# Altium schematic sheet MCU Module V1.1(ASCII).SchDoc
size 420 x 297 mm
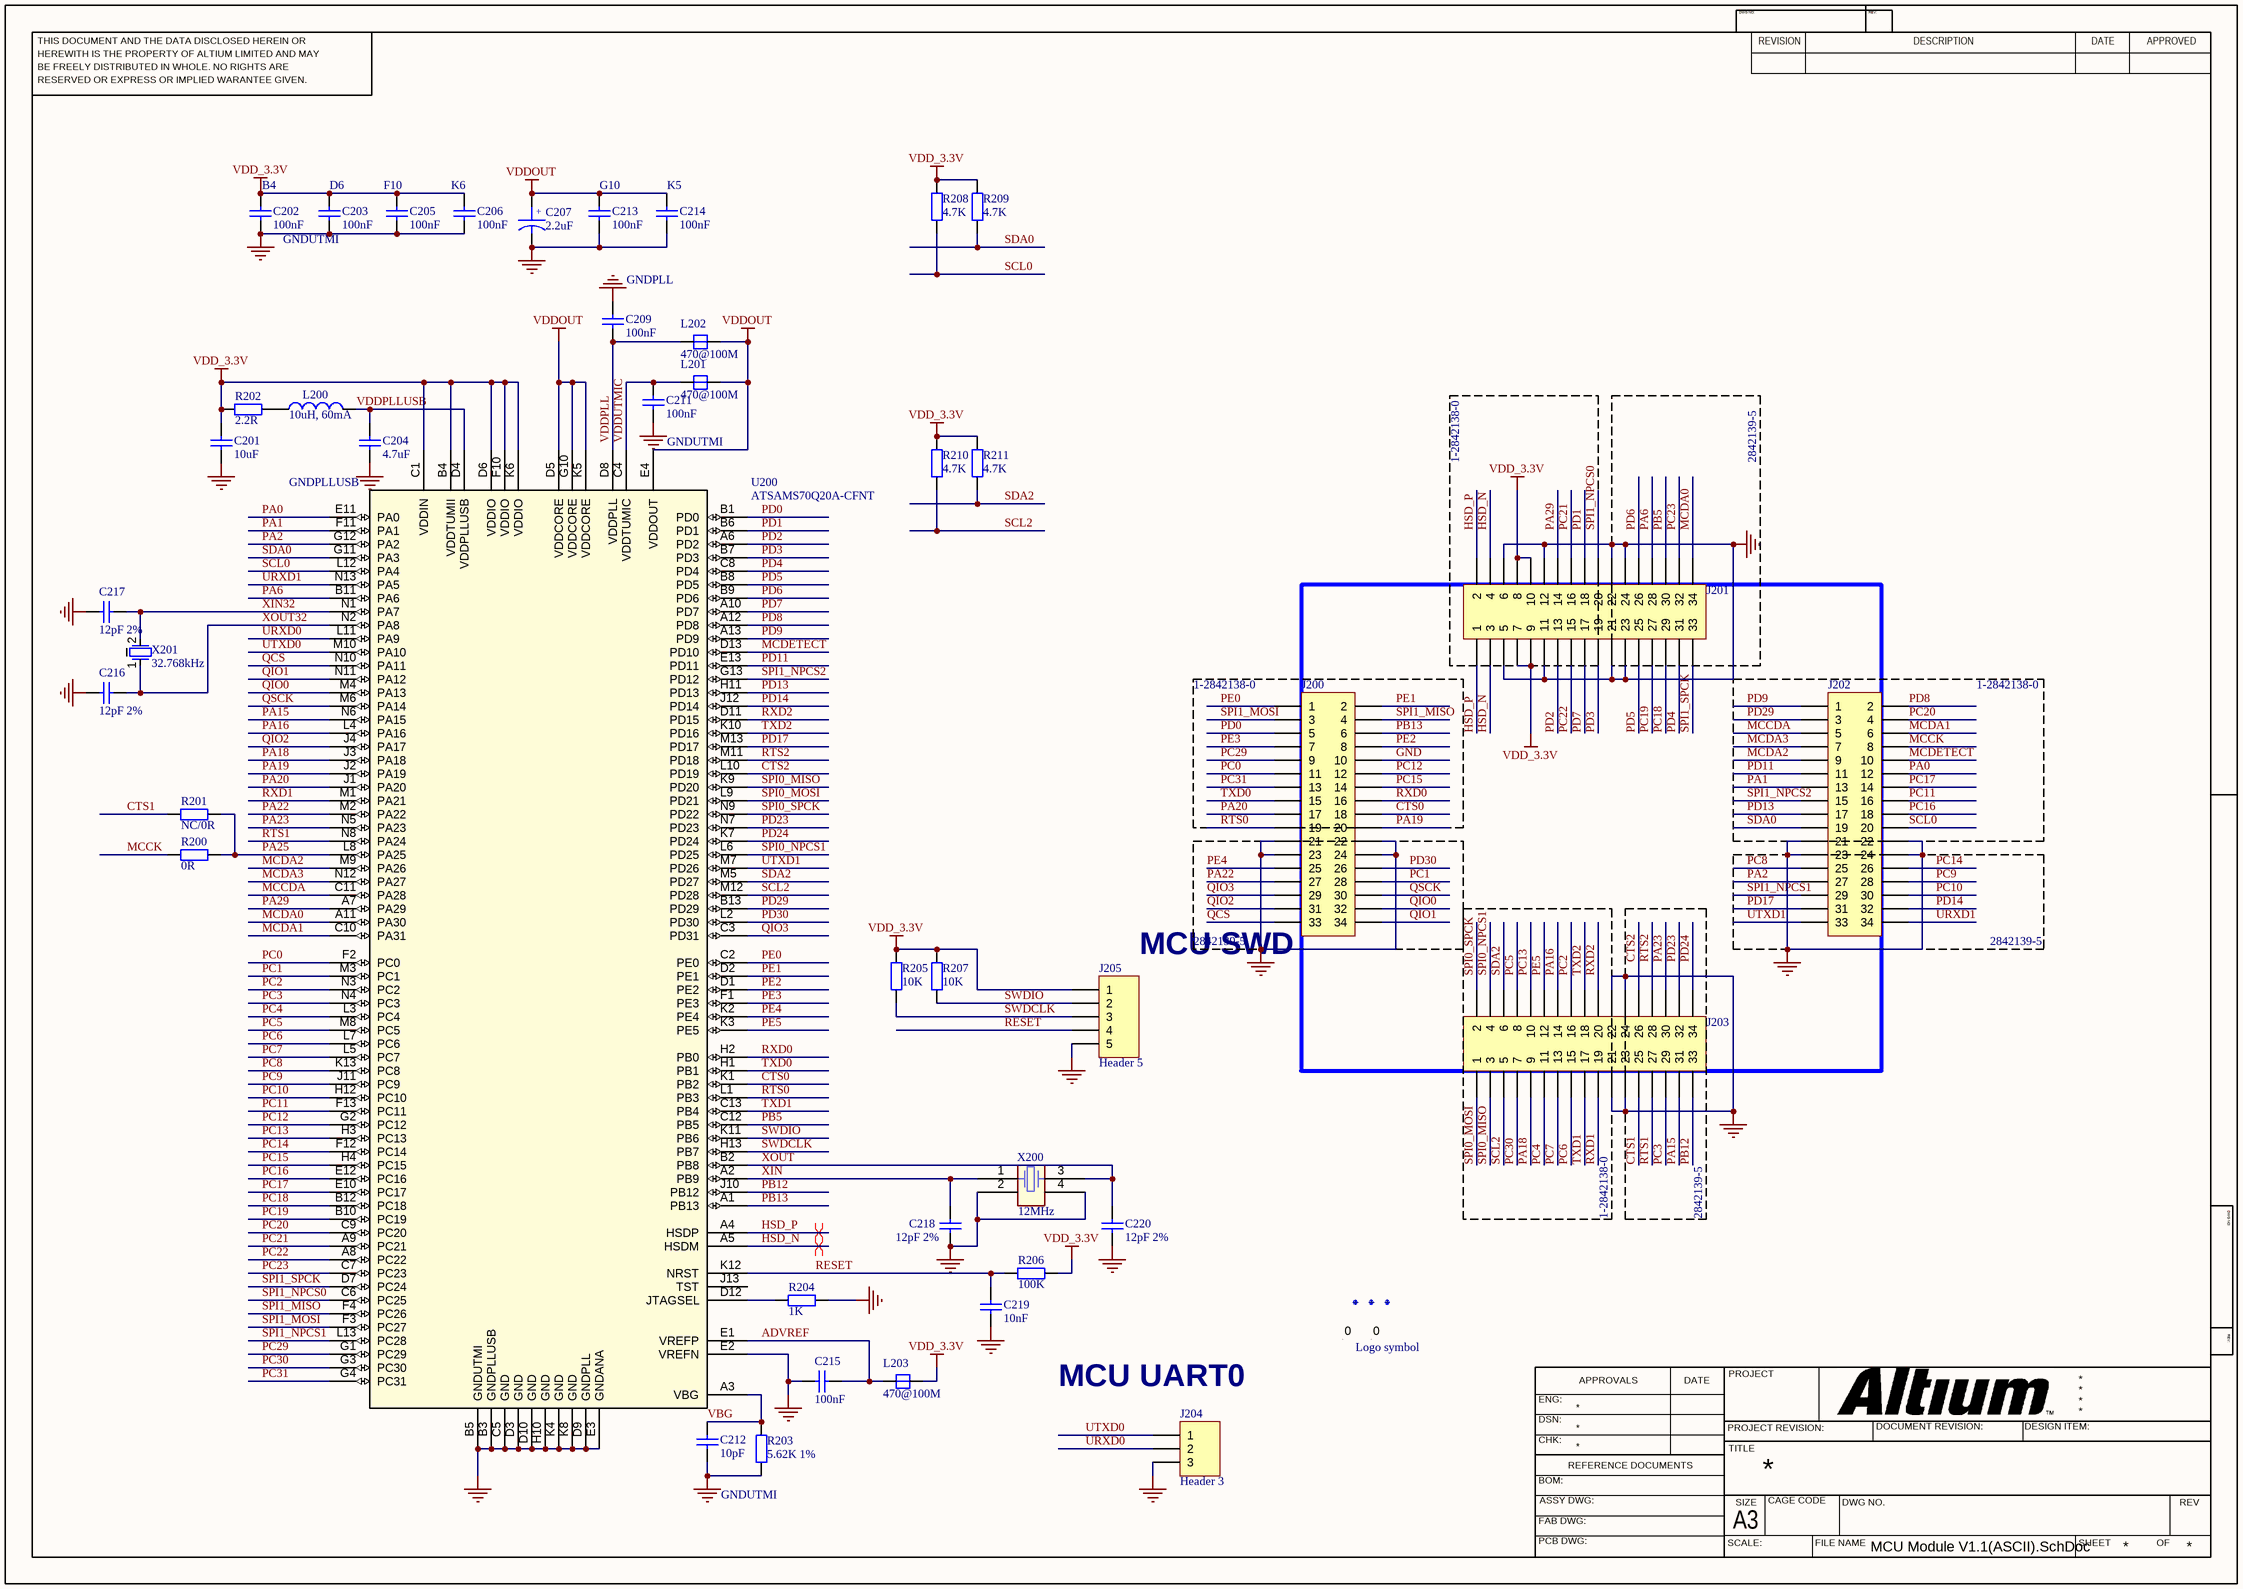
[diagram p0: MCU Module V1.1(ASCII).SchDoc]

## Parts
C201  10uF  [C_0805_2012Metric]
C202  100nF  [C_0805_2012Metric]
C203  100nF  [C_0805_2012Metric]
C204  4.7uF  [C_0805_2012Metric]
C205  100nF  [C_0805_2012Metric]
C206  100nF  [C_0805_2012Metric]
C207  2.2uF  [C_TAN_1206_3216METRIC]
C209  100nF  [C_0805_2012Metric]
C211  100nF  [C_0805_2012Metric]
C212  10pF  [C_0805_2012Metric]
C213  100nF  [C_0805_2012Metric]
C214  100nF  [C_0805_2012Metric]
C215  100nF  [C_0805_2012Metric]
C216  12pF 2%  [C_0805_2012Metric]
C217  12pF 2%  [C_0805_2012Metric]
C218  12pF 2%  [C_0805_2012Metric]
C219  10nF  [C_0805_2012Metric]
C220  12pF 2%  [C_0805_2012Metric]
Fid1  Fiducial mark  [Fiducial_1mm_Mask2mm]  (value not drawn)  (no BOM)
Fid2  Fiducial mark  [Fiducial_1mm_Mask2mm]  (value not drawn)  (no BOM)
Fid3  Fiducial mark  [Fiducial_1mm_Mask2mm]  (value not drawn)  (no BOM)
J200  Header 17X2  [HDR-TH_34P-P2.00-V-M-R2-C17-S2.00 - MALE]  (value not drawn)
J201  Header 17X2  [HDR-TH_34P-P2.00-V-M-R2-C17-S2.00 - MALE]  (value not drawn)
J202  Header 17X2  [HDR-TH_34P-P2.00-V-M-R2-C17-S2.00 - MALE]  (value not drawn)
J203  Header 17X2  [HDR-TH_34P-P2.00-V-M-R2-C17-S2.00 - MALE]  (value not drawn)
J204  Header 3  [PinHeader_1x03_P2.54mm_Vertical]
J205  Header 5  [PinHeader_1x05_P2.54mm_Vertical]
L200  10uH, 60mA  [L_0603_1608Metric]
L201  470@100M  [L_0603_1608Metric]
L202  470@100M  [L_0603_1608Metric]
L203  470@100M  [L_0603_1608Metric]
Logo_Bot?  Logo symbol  [CE-Logo_8.5x6mm_SilkScreen]  (value not drawn)
Logo_Top?  Logo symbol  [WEEE-Logo_4.2x6mm_SilkScreen]
R200  0R  [R_0805_2012Metric]
R201  NC/0R  [R_0805_2012Metric]
R202  2.2R  [R_0805_2012Metric]
R203  5.62K 1%  [R_0805_2012Metric]
R204  1K  [R_0805_2012Metric]
R205  10K  [R_0805_2012Metric]
R206  100K  [R_0805_2012Metric]
R207  10K  [R_0805_2012Metric]
R208  4.7K  [R_0805_2012Metric]
R209  4.7K  [R_0805_2012Metric]
R210  4.7K  [R_0805_2012Metric]
R211  4.7K  [R_0805_2012Metric]
U200  ATSAMS70Q20A-CFNT  [UFBGA144(6x6mm)]
X200  12MHz  [CRY-3225]
X201  32.768kHz  [Crystal 1.8x6mmm]

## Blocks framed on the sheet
1-2842138-0: J201
1-2842138-0: J200
1-2842138-0: J202

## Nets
GND: C201.2 C202.2 C203.2 C204.2 C205.2 C206.2 C207.2 C209.1 C211.2 C212.1 C213.2 C214.2 C215.1 C216.1 C217.1 C218.1 C219.2 C220.1 J200.10 J200.21 J200.22 J200.23 J200.24 J201.5 J201.6 J201.11 J201.12 J201.21 J201.22 J201.23 J201.24 J202.21 J202.22 J202.23 J202.24 J203.21 J203.22 J203.23 J203.24 J204.3 J205.5 R203.1 R204.1 U200.B3(GNDPLLUSB) U200.B5(GNDUTMI) U200.C5(GND) U200.D3(GND) U200.D9(GNDPLL) U200.D10(GND) U200.E2(VREFN) U200.E3(GNDANA) U200.H10(GND) U200.K4(GND) U200.K8(GND) X200.2 X200.4
VDD_3.3V: C201.1 C202.1 C203.1 C205.1 C206.1 J201.7 J201.8 J201.9 J201.10 J205.1 L203.2 R202.2 R205.2 R206.1 R207.2 R208.2 R209.2 R210.2 R211.2 U200.B4(VDDTUMII) U200.C1(VDDIN) U200.D6(VDDIO) U200.F10(VDDIO) U200.K6(VDDIO)
VDDOUT: C207.1 C213.1 C214.1 L201.2 L202.2 U200.D5(VDDCORE) U200.E4(VDDOUT) U200.G10(VDDCORE) U200.K5(VDDCORE)
ADVREF: C215.2 L203.1 U200.E1(VREFP)
CTS0: J200.18 U200.K1(PB2)
CTS1: J203.25 R201.2
CTS2: J203.26 U200.L10(PD19)
HSD_N: J201.3 J201.4 U200.A5(HSDM)
HSD_P: J201.1 J201.2 U200.A4(HSDP)
MCCDA: J202.5 U200.C11(PA28)
MCCK: J202.8 R200.2
MCDA0: J201.34 U200.A11(PA30)
MCDA1: J202.6 U200.C10(PA31)
MCDA2: J202.9 U200.M9(PA26)
MCDA3: J202.7 U200.N12(PA27)
MCDETECT: J202.10 U200.D13(PD10)
PA0: J202.12 U200.E11(PA0)
PA1: J202.13 U200.F11(PA1)
PA2: J202.27 U200.G12(PA2)
PA6: J201.28 U200.B11(PA6)
PA15: J203.31 U200.N6(PA15)
PA16: J203.14 U200.L4(PA16)
PA18: J203.9 U200.J3(PA18)
PA19: J200.20 U200.J2(PA19)
PA20: J200.17 U200.J1(PA20)
PA22: J200.27 U200.M2(PA22)
PA23: J203.30 U200.N5(PA23)
PA25: R200.1 R201.1 U200.L8(PA25)
PA29: J201.14 U200.A7(PA29)
PB5: J201.30 U200.C12(PB5)
PB12: J203.33 U200.J10(PB12)
PB13: J200.6 U200.A1(PB13)
PC0: J200.11 U200.F2(PC0)
PC1: J200.28 U200.M3(PC1)
PC2: J203.16 U200.N3(PC2)
PC3: J203.29 U200.N4(PC3)
PC4: J203.11 U200.L3(PC4)
PC5: J203.8 U200.M8(PC5)
PC6: J203.15 U200.L7(PC6)
PC7: J203.13 U200.L5(PC7)
PC8: J202.25 U200.K13(PC8)
PC9: J202.28 U200.J11(PC9)
PC10: J202.30 U200.H12(PC10)
PC11: J202.16 U200.F13(PC11)
PC12: J200.12 U200.G2(PC12)
PC13: J203.10 U200.H3(PC13)
PC14: J202.26 U200.F12(PC14)
PC15: J200.14 U200.H4(PC15)
PC16: J202.18 U200.E12(PC16)
PC17: J202.14 U200.E10(PC17)
PC18: J201.29 U200.B12(PC18)
PC19: J201.27 U200.B10(PC19)
PC20: J202.4 U200.C9(PC20)
PC21: J201.16 U200.A9(PC21)
PC22: J201.15 U200.A8(PC22)
PC23: J201.32 U200.C7(PC23)
PC29: J200.9 U200.G1(PC29)
PC30: J203.7 U200.G3(PC30)
PC31: J200.13 U200.G4(PC31)
PD0: J200.5 U200.B1(PD0)
PD1: J201.18 U200.B6(PD1)
PD2: J201.13 U200.A6(PD2)
PD3: J201.19 U200.B7(PD3)
PD4: J201.31 U200.C8(PD4)
PD5: J201.25 U200.B8(PD5)
PD6: J201.26 U200.B9(PD6)
PD7: J201.17 U200.A10(PD7)
PD8: J202.2 U200.A12(PD8)
PD9: J202.1 U200.A13(PD9)
PD11: J202.11 U200.E13(PD11)
PD13: J202.17 U200.H11(PD13)
PD14: J202.32 U200.J12(PD14)
PD17: J202.31 U200.M13(PD17)
PD23: J203.32 U200.N7(PD23)
PD24: J203.34 U200.K7(PD24)
PD29: J202.3 U200.B13(PD29)
PD30: J200.26 U200.L2(PD30)
PE0: J200.1 U200.C2(PE0)
PE1: J200.2 U200.D2(PE1)
PE2: J200.8 U200.D1(PE2)
PE3: J200.7 U200.F1(PE3)
PE4: J200.25 U200.K2(PE4)
PE5: J203.12 U200.K3(PE5)
QCS: J200.33 U200.N10(PA11)
QIO0: J200.32 U200.M4(PA13)
QIO1: J200.34 U200.N11(PA12)
QIO2: J200.31 U200.J4(PA17)
QIO3: J200.29 U200.C3(PD31)
QSCK: J200.30 U200.M6(PA14)
RESET: C219.1 J205.4 R206.2 U200.K12(NRST)
RTS0: J200.19 U200.L1(PB3)
RTS1: J203.27 U200.N8(PA24)
RTS2: J203.28 U200.M11(PD18)
RXD0: J200.16 U200.H2(PB0)
RXD1: J203.19 U200.M1(PA21)
RXD2: J203.20 U200.D11(PD15)
SCL0: J202.20 R208.1 U200.L12(PA4)
SCL2: J203.5 R210.1 U200.M12(PD28)
SDA0: J202.19 R209.1 U200.G11(PA3)
SDA2: J203.6 R211.1 U200.M5(PD27)
SPI0_MISO: J203.3 U200.K9(PD20)
SPI0_MOSI: J203.1 U200.L9(PD21)
SPI0_NPCS1: J203.4 U200.L6(PD25)
SPI0_SPCK: J203.2 U200.N9(PD22)
SPI1_MISO: J200.4 U200.F4(PC26)
SPI1_MOSI: J200.3 U200.F3(PC27)
SPI1_NPCS0: J201.20 U200.C6(PC25)
SPI1_NPCS1: J202.29 U200.L13(PC28)
SPI1_NPCS2: J202.15 U200.G13(PD12)
SPI1_SPCK: J201.33 U200.D7(PC24)
SWDCLK: J205.3 R205.1 U200.H13(PB7)
SWDIO: J205.2 R207.1 U200.K11(PB6)
TXD0: J200.15 U200.H1(PB1)
TXD1: J203.17 U200.C13(PB4)
TXD2: J203.18 U200.K10(PD16)
URXD0: J204.2 U200.L11(PA9)
URXD1: J202.34 U200.N13(PA5)
UTXD0: J204.1 U200.M10(PA10)
UTXD1: J202.33 U200.M7(PD26)
VBG: C212.2 R203.2 U200.A3(VBG)
VDDPLL: C209.2 L202.1 U200.D8(VDDPLL)
VDDPLLUSB: C204.1 L200.1 U200.D4(VDDPLLUSB)
VDDUTMIC: C211.1 L201.1 U200.C4(VDDTUMIC)
XIN: C218.2 U200.A2(PB9) X200.1
XIN32: C217.2 U200.N1(PA7) X201.2
XOUT: C220.2 U200.B2(PB8) X200.3
XOUT32: C216.2 U200.N2(PA8) X201.1
NetL200_2: L200.2 R202.1
NetR204_2: R204.2 U200.D12(JTAGSEL)

Not connected (* = marked no-connect by the designer): Logo_Bot? 0; Logo_Top? 0; U200 J13(TST)

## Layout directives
differential pair; differential pair class 90ohm; net class 90ohm: HSD_N, HSD_P

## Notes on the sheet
- (near C202) B4
- (near C203) D6
- (near C205) F10
- (near C206) K6
- (near C213) G10
- (near C214) K5
- (near C203) GNDUTMI
- (near C209) GNDPLL
- GNDUTMI
- 2842139-5
- GNDPLLUSB
- (near J205) MCU SWD
- 1-2842138-0
- (near J204) MCU UART0

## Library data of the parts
C201 = Cap Semi: CAP CER 10UF 6.3V X5R 0805
C202 C203 C205 C206 C209 C211 C213-C215 = Cap Semi: CAP CER 0.1UF 25V X7R 0805
C204 = Cap Semi: CAP CER 4.7UF 10V X5R 0805
C207 = A01-0492: Capacitor Tantalum 10V 2.2uF 10% ESR = 6 ohm; PartGroup: Capacitors,Tantalum; Manufacturer: Kemet; MPN: T494A225K010AT; TemperatureRange: - 55 C to + 125 C
C212 = Cap Semi: CAP CER 10PF 100V C0G/NP0 0805
C216-C218 C220 = Cap Semi: CAP CER 12PF 50V C0G/NP0 0805
C219 = Cap Semi: CAP CER 10000PF 10V X7R 0805
Fid1-Fid3 = Fiducial: Part Number: Fid-Mark; Artikkelnr Noca: N.A.
J200-J203 = Header 17X2: Header, 17-Pin, Dual row
J204 = Header 3: Header, 3-Pin
J205 = Header 5: CONN HEADER VERT 5POS 2MM
L200 = A03-0035: FIXED IND 10UH 60MA 700 MOHM SMD; PartGroup: Inductors,EMI; Manufacturer: Murata; MPN: BLM18PG471SN1; TemperatureRange: -55
L201-L203 = FB-M1331: FERRITE BEAD 470 OHM 0603 1LN; GateName_1: G$1; SymbolName_1: FB; DeviceName: -M1331
Logo_Bot? Logo_Top? = Logo: Schematic symbol for Logo
R200 R201 = Res2: RES 0 OHM JUMPER 1/8W 0805
R202 = Res2: RES 2.2 OHM 5% 1/8W 0805
R203 = Res2: RES 5.62K OHM 1% 1/8W 0805
R204 = Res2: RES 1K OHM 1% 1/8W 0805
R205 R207 = Res2: RES 10K OHM 5% 1/8W 0805
R206 = Res2: RES 100K OHM 5% 1/8W 0805
R208-R211 = Res2: RES 4.7K OHM 5% 1/8W 0805
U200 = ATSAMS70Q20A-CFNT: 32-bit ARM Cortex-M7 MCUs with FPU, Audio andGraphics Interfaces, High-Speed USB, Ethernet, andAdvanced Analog; Manufacturer_Part_Number: ATSAMS70Q20A-CNT; Vendor: Microchip; Built_By: EMA_Molly; SourceLibrary: Microchip_2019-08-23_25
X200 = A07-0042: CRYSTAL 12.0000MHZ 18PF SMD; PartGroup: Frequency devices,Crystals,SMD; Manufacturer: Fox  Electronics; MPN: FQ5032B-12.000; Value: 12.00MHz; Tolerance: Â±30ppm; TemperatureRange: 0Â°C ~ 70Â°C
X201 = A07-0052: CRYSTAL 32.7680KHZ 12.5PF SMD; PartGroup: Frequency devices,Crystals,SMD; Manufacturer: Micro Crystal; MPN: MS1V-T1K 32.768kHz 7pF +/-20PPM TA; Tolerance: +/- 20 PPM; TemperatureRange: -40 /+85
